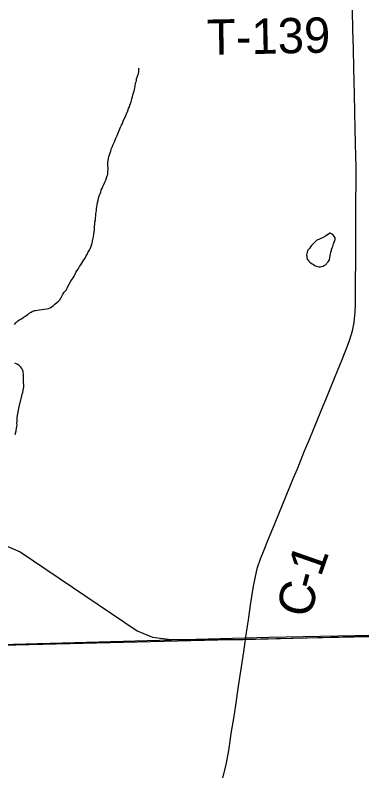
# Model space of a CAD drawing. Extents: x 103424 to 290657, y 38711 to 110967.
# Drawn here: x 154860 to 157824, y 43242 to 49697 of the extents above; entities that cross this region are included whole.
import ezdxf

# ---------------------------------------------------------------- set-up
doc = ezdxf.new("R2010")
doc.units = 0
for name, color, linetype in [('GM_X_Corporation', 7, 'Continuous'), ('GM_X_County_Road', 7, 'Continuous'), ('GM_X_County_Road_Text', 7, 'Continuous'), ('GM_X_Minor_Lake', 7, 'Continuous'), ('GM_X_Minor_River', 7, 'Continuous'), ('GM_X_Rail_Line', 7, 'Continuous'), ('GM_X_Township_Road_Text', 7, 'Continuous')]:
    doc.layers.add(name, color=color, linetype=linetype)

msp = doc.modelspace()

# ---------------------------------------------------------------- linework, layer by layer
at = {"layer": 'GM_X_Corporation'}
msp.add_lwpolyline([(167441.7, 44516.4), (162024.2, 44473.4), (156824.1, 44363.7), (149451.3, 44180.8), (149440.5, 44755.1), (149429.7, 45329.4), (149418.4, 46068), (149363.3, 49922), (149355.7, 51621.4), (149274.7, 56114.3), (149214.2, 60733.4)], dxfattribs=at)
for points in [[(149532.9, 38711.2), (174769.9, 38711.2), (174768.4, 38806.4), (174722.1, 40540.3), (174610.2, 44665.1), (172842.5, 44649), (172841.3, 44649), (167441.7, 44516.4), (162024.2, 44473.4), (156824.1, 44363.7), (149451.3, 44180.8), (149476.1, 42604.7), (149528, 39851)], [(154672.6, 38711.2), (159127.7, 38711.2), (159759.8, 38726.2), (159627, 44430), (159529.4, 44428), (157027.9, 44382), (154532, 44312.4)]]:
    msp.add_lwpolyline(points, close=True, dxfattribs=at)
at = {"layer": 'GM_X_County_Road'}
msp.add_line((156832.8, 44386.5), (156837.9, 44423.1), dxfattribs=at)
for points in [[(156837.9, 44423.1), (156853.3, 44532.6), (156874.9, 44676.4), (156896.5, 44820.2), (156921.8, 44941.3), (156932, 44978.7), (156956, 45052.1), (156988.1, 45130.2), (157020.2, 45208.3), (157083, 45361), (157145.7, 45513.7), (157208.4, 45666.3), (157240.3, 45744.1), (157272.2, 45821.8), (157334.5, 45974.7), (157371.8, 46066.3), (157409.2, 46157.8), (157471.8, 46310.6), (157534.4, 46463.3), (157594.5, 46609.6), (157654.5, 46756), (157681.4, 46820.9), (157704.9, 46877.9), (157721.3, 46926.4), (157742.9, 47000.4), (157756.7, 47070.5), (157765.2, 47162.2), (157769.1, 47221.1), (157768.5, 47305.6), (157768.8, 47391.1), (157770.5, 47626.7), (157771.7, 47719), (157772.4, 48142.2), (157773.4, 48229), (157774.4, 48315.8), (157773.7, 48401.3), (157773.1, 48486.8), (157770.1, 48604.7), (157767.2, 48722.6), (157763.6, 48870.4), (157760, 49018.1), (157758, 49131.4), (157756, 49244.8), (157751.5, 49409.8), (157747.1, 49574.8), (157742.6, 49737.9)], [(156636.3, 43182.1), (156662.9, 43292.1), (156685.8, 43416.7), (156710.8, 43577.6), (156728, 43690.1), (156745.2, 43802.7), (156769.7, 43965.9), (156794.2, 44129.2), (156813.5, 44257.8), (156832.8, 44386.5)]]:
    msp.add_lwpolyline(points, dxfattribs=at)
at = {"layer": 'GM_X_Minor_Lake'}
for points in [[(157549.7, 47835.2), (157513.9, 47808.1), (157493.9, 47797.6), (157471.9, 47789.1), (157455.9, 47780.6), (157439.8, 47774.2), (157429.9, 47765.9), (157418, 47755.6), (157406.2, 47743.2), (157394.3, 47728.8), (157384.4, 47718.5), (157374.6, 47704.2), (157362.8, 47689.8), (157355.1, 47671.5), (157353.4, 47657.3), (157351.6, 47647.2), (157351.8, 47637.1), (157352, 47627), (157356.4, 47610.9), (157368.9, 47595.1), (157379.2, 47587.2), (157397.7, 47571.4), (157410, 47565.7), (157420.2, 47557.8), (157432.5, 47552), (157444.7, 47548.3)], [(157549.7, 47835.2), (157513.9, 47808.1), (157493.9, 47797.6), (157471.9, 47789.1), (157455.9, 47780.6), (157439.8, 47774.2), (157429.9, 47765.9), (157418, 47755.6), (157406.2, 47743.2), (157394.3, 47728.8), (157384.4, 47718.5), (157374.6, 47704.2), (157362.8, 47689.8), (157355.1, 47671.5), (157353.4, 47657.3), (157351.6, 47647.2), (157351.8, 47637.1), (157352, 47627), (157356.4, 47610.9), (157368.9, 47595.1), (157379.2, 47587.2), (157397.7, 47571.4), (157410, 47565.7), (157420.2, 47557.8), (157432.5, 47552), (157444.7, 47548.3), (157456.8, 47546.5), (157471, 47546.8), (157493.1, 47553.3), (157503.1, 47559.6), (157517, 47568), (157524.9, 47578.2), (157536.8, 47590.6), (157546.5, 47607), (157550.2, 47625.2), (157551.9, 47639.4), (157555.5, 47657.6), (157559.3, 47671.8), (157563, 47686.1), (157564.8, 47696.2), (157568.6, 47708.4), (157574.4, 47720.6), (157578.2, 47730.8), (157582, 47743), (157587.7, 47759.3), (157591.5, 47769.4), (157595.3, 47783.7), (157595, 47795.8), (157574.2, 47821.6), (157557.9, 47831.3), (157551.8, 47833.2), (157549.7, 47835.2)], [(157444.7, 47548.3), (157456.8, 47546.5), (157471, 47546.8), (157493.1, 47553.3), (157503.1, 47559.6), (157517, 47568), (157524.9, 47578.2), (157536.8, 47590.6), (157546.5, 47607), (157550.2, 47625.2), (157551.9, 47639.4), (157555.5, 47657.6), (157559.3, 47671.8), (157563, 47686.1), (157564.8, 47696.2), (157568.6, 47708.4), (157574.4, 47720.6), (157578.2, 47730.8), (157582, 47743), (157587.7, 47759.3), (157591.5, 47769.4), (157595.3, 47783.7), (157595, 47795.8), (157574.2, 47821.6), (157557.9, 47831.3), (157551.8, 47833.2), (157549.7, 47835.2)]]:
    msp.add_lwpolyline(points, dxfattribs=at)
at = {"layer": 'GM_X_Minor_River'}
for points in [[(155738.9, 48682), (155742.6, 48696.2), (155750.3, 48712.5), (155756.1, 48726.8), (155761.9, 48739), (155769.6, 48755.4), (155777.4, 48771.7), (155785.1, 48790), (155792.7, 48810.4), (155802.4, 48830.8), (155810.1, 48849.1), (155817.8, 48865.4), (155823.6, 48879.7), (155829.2, 48900), (155837, 48914.3), (155840.7, 48926.5), (155846.5, 48942.7), (155852.2, 48957), (155856, 48969.2), (155857.8, 48981.3), (155863.5, 48997.6), (155867.1, 49015.9), (155870.8, 49032.1), (155876.5, 49048.4), (155880.3, 49062.6), (155882, 49074.7), (155885.8, 49086.9), (155887.6, 49097.1), (155889.3, 49111.2), (155893.1, 49125.4), (155896.9, 49135.6), (155898.6, 49151.8), (155904.3, 49166), (155908, 49184.3), (155913.8, 49194.5), (155917.4, 49214.8), (155918.9, 49239), (155920.8, 49245.1)], [(154913.7, 47103.6), (154929.6, 47114.1), (154947.6, 47124.6), (154961.6, 47132.9), (154971.5, 47141.2), (154979.4, 47151.5), (154991.4, 47155.8), (155007.4, 47164.2), (155025.4, 47172.7), (155037.5, 47175), (155051.6, 47177.3), (155067.7, 47179.6), (155087.9, 47182.1), (155106, 47184.5), (155130.2, 47187.1), (155146.3, 47191.4), (155160.3, 47197.8), (155172.3, 47204.1), (155184.2, 47212.5), (155200.1, 47226.9), (155217.9, 47241.5), (155231.8, 47253.9), (155241.7, 47266.2), (155253.4, 47284.6), (155265.1, 47307.1), (155280.7, 47331.6), (155298.5, 47350.2), (155308.1, 47372.6), (155321.7, 47399.2), (155335.3, 47423.7), (155347.1, 47440.1), (155356.9, 47452.4), (155364.7, 47466.7), (155372.4, 47483), (155380.2, 47497.3), (155388, 47511.6), (155397.8, 47526), (155411.5, 47548.5), (155421.2, 47564.8), (155448.6, 47605.8), (155458.4, 47622.2), (155468.1, 47640.5), (155477.8, 47658.9), (155485.6, 47675.2), (155495.3, 47689.6), (155501.2, 47701.8), (155506.9, 47716.1), (155512.6, 47732.3), (155518.3, 47748.6), (155522, 47764.9), (155525.7, 47781.1), (155529.3, 47803.4), (155532.9, 47825.7), (155536.5, 47845.9), (155538.1, 47866.1), (155539.6, 47890.4), (155541.1, 47912.6), (155542.8, 47928.8), (155546.4, 47949.1), (155548.1, 47965.3), (155549.7, 47983.5), (155551.3, 48003.7), (155554.8, 48026), (155556.5, 48044.2), (155558.2, 48058.3), (155561.8, 48076.6), (155565.5, 48096.9), (155569.1, 48115.1), (155572.8, 48129.3), (155576.5, 48145.6), (155582.3, 48157.8), (155586.1, 48170), (155591.9, 48184.2), (155595.6, 48200.5), (155603.3, 48214.8), (155609, 48233.1), (155618.7, 48251.4), (155628.4, 48269.8), (155634.2, 48286.1), (155641.8, 48306.4), (155647.5, 48324.7), (155651.3, 48334.9), (155653, 48349.1), (155652.7, 48365.2), (155654.4, 48379.4), (155654.1, 48393.5), (155653.8, 48405.6), (155653.5, 48419.7), (155653.2, 48435.9), (155658.5, 48472.3), (155660.1, 48488.5), (155665.9, 48504.8), (155671.6, 48521.1), (155677.3, 48535.3), (155681, 48551.6), (155688.7, 48569.9), (155698.4, 48590.3), (155710, 48614.8), (155721.5, 48645.3), (155733.1, 48667.7), (155738.9, 48682)], [(154856.2, 47053.9), (154867.9, 47072.4), (154883.7, 47086.8), (154897.7, 47095.2), (154913.7, 47103.6)], [(154860.1, 46115.3), (154869.5, 46145.8), (154873, 46170.1), (154876.6, 46194.4), (154876.2, 46210.5), (154877.8, 46232.8), (154879.2, 46261.1), (154882.6, 46291.4), (154887.9, 46323.8), (154895.4, 46352.3), (154917.7, 46445.6), (154921.4, 46459.8), (154925.2, 46474), (154928.8, 46492.3), (154932.5, 46508.5), (154934.3, 46520.7), (154934, 46534.8), (154933.4, 46561), (154930.6, 46597.3), (154932.2, 46617.5), (154931.9, 46629.6), (154929.6, 46641.7), (154929.4, 46651.8), (154923.1, 46665.8), (154918.7, 46679.8), (154910.4, 46689.7), (154896, 46703.5), (154883.7, 46711.3), (154871.4, 46717.1), (154857.2, 46722.9)]]:
    msp.add_lwpolyline(points, dxfattribs=at)
at = {"layer": 'GM_X_Rail_Line'}
msp.add_lwpolyline([(146504.9, 45437.9), (151249.2, 45325.6), (154443.7, 45236.2), (154715.5, 45192.7), (154903.9, 45112.9), (155904.2, 44438.6), (156034.7, 44384.2), (156194.1, 44362.5), (156810.2, 44362.5), (161177.6, 44481.6), (161906.5, 44481.2), (168026.1, 44546.6), (168178.1, 44543.3), (168898.2, 44555.7), (171103.9, 46845), (171363.9, 47125.7), (171451.7, 47389.1), (171481, 47646.7), (171393.2, 47915.9), (171381.5, 48056.4), (171404.9, 48167.6), (171498.5, 48308.1), (174523.8, 51299.4), (175679.7, 52376.9)], dxfattribs=at)

# ---------------------------------------------------------------- texts
at = {"layer": 'GM_X_County_Road_Text'}
for s, rotation, p in [('1', 70.69939, (157471.4, 44890.9)), ('-', 75.00572, (157441, 44776.9)), ('C', 76.35564, (157383, 44537.7))]:
    msp.add_text(s, height=301.9, rotation=rotation, dxfattribs=at).set_placement(p)
at = {"layer": 'GM_X_Township_Road_Text'}
msp.add_text('T-139', height=301.87, rotation=1.12366, dxfattribs=at).set_placement((156502, 49356.4))

doc.saveas('drawing.dxf')
